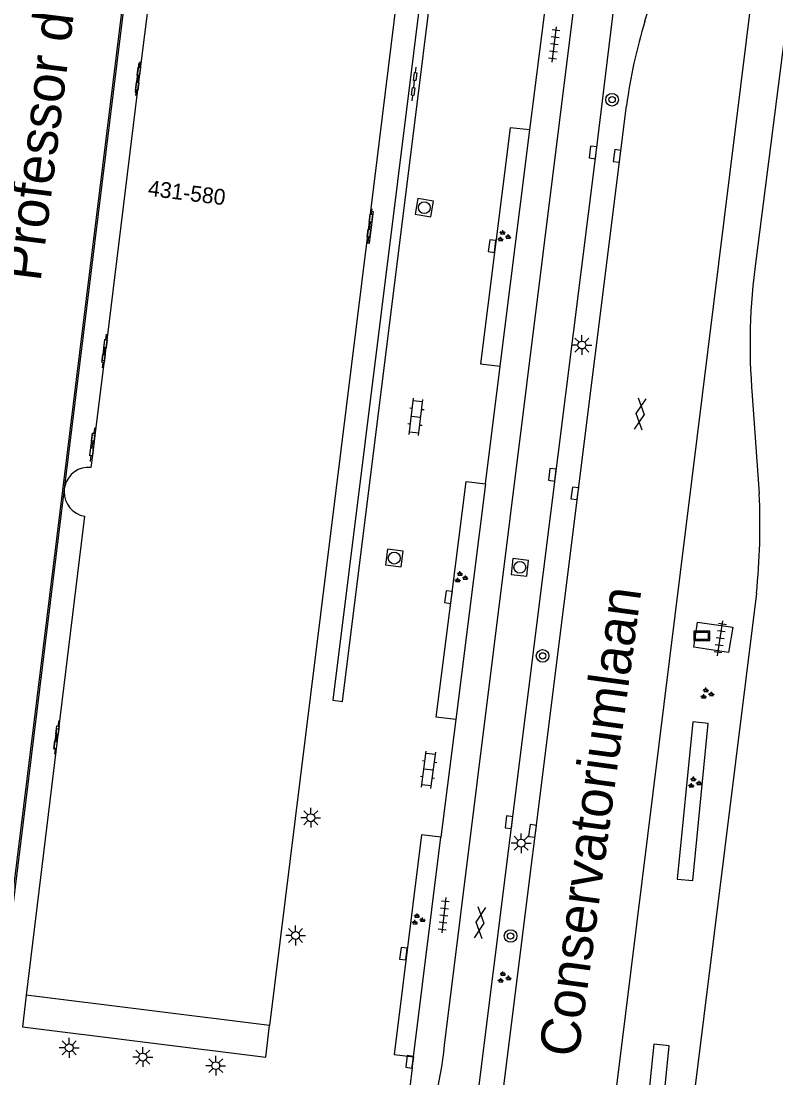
# Model space of a CAD drawing. Extents: x 131000 to 133014, y 396499 to 399001.
# Drawn here: x 131618.1 to 131665.8, y 397040.1 to 397107 of the extents above; entities that cross this region are included whole.
import ezdxf

# ---------------------------------------------------------------- set-up
doc = ezdxf.new("R2010")
doc.units = 0
for name, color, linetype in [('gg-anno-huisnummerreeks BGT', 7, 'Continuous'), ('gg-anno-openbare ruimte label', 7, 'Continuous'), ('gg-bbg-hoofdgebouw', 7, 'Continuous'), ('gg-bbg-onder overbouw', 7, 'Continuous'), ('gg-bbg-pand overbouw', 7, 'Continuous'), ('gg-knt-verharding', 7, 'Continuous'), ('gt-grn-afwateringsgoot', 7, 'Continuous'), ('gt-grn-groengrens', 7, 'Continuous'), ('gt-symb-afwateringsgoot', 7, 'Continuous'), ('gt-symb-boom', 7, 'Continuous'), ('gt-symb-gesloten verharding', 7, 'Continuous'), ('gt-symb-groenvak', 7, 'Continuous'), ('gt-symb-klinker verharding', 7, 'Continuous'), ('gt-symb-kolk', 7, 'Continuous'), ('gt-symb-lichtmast', 7, 'Continuous'), ('gt-symb-reclamebord', 7, 'Continuous'), ('gt-symb-rioolschacht', 7, 'Continuous'), ('gt-symb-tegel verharding', 7, 'Continuous')]:
    doc.layers.add(name, color=color, linetype=linetype)

# ---------------------------------------------------------------- blocks, each defined once
blk = doc.blocks.new('gt0-GRVAK')
at = {"layer": 'gt-symb-groenvak'}
for p, q in [((-0.11, 0.189), (-0.228, 0.24)), ((-0.182, 0.153), (0.088, 0.153)), ((-0.091, 0.211), (-0.156, 0.322)), ((-0.047, 0.214), (-0.047, 0.393)), ((-0.004, 0.211), (0.061, 0.322)), ((0.015, 0.189), (0.133, 0.24)), ((0.262, -0.052), (0.197, 0.059)), ((0.305, -0.049), (0.305, 0.13)), ((0.349, -0.052), (0.414, 0.059)), ((-0.245, -0.228), (-0.363, -0.177)), ((-0.318, -0.264), (-0.047, -0.264)), ((-0.226, -0.206), (-0.291, -0.095)), ((-0.183, -0.203), (-0.183, -0.024)), ((-0.139, -0.206), (-0.074, -0.095)), ((-0.12, -0.228), (-0.002, -0.177)), ((0.243, -0.074), (0.125, -0.023)), ((0.17, -0.11), (0.441, -0.11)), ((0.368, -0.074), (0.486, -0.023))]:
    blk.add_line(p, q, dxfattribs=at)
blk = doc.blocks.new('gt0-BOOM')
at = {"layer": 'gt-symb-boom'}
for radius in [0.4, 0.2]:
    blk.add_circle((0, 0), radius, dxfattribs=at)
blk = doc.blocks.new('gt0-TEG1')
at = {"layer": 'gt-symb-tegel verharding'}
for p, q in [((-1.125, 0), (1.125, 0)), ((-0.9, -0.25), (-0.9, 0.25)), ((-0.45, -0.25), (-0.45, 0.25)), ((0, -0.25), (0, 0.25)), ((0.45, -0.25), (0.45, 0.25)), ((0.9, -0.25), (0.9, 0.25))]:
    blk.add_line(p, q, dxfattribs=at)
blk = doc.blocks.new('gt0-RBORD')
at = {"layer": 'gt-symb-reclamebord'}
blk.add_lwpolyline([(-0.5, 0.295), (-0.5, -0.295), (0.5, -0.295), (0.5, 0.295), (-0.5, 0.295)], dxfattribs=at)
blk.add_lwpolyline([(-0.417, -0.212), (0.417, -0.212), (0.417, 0.212), (-0.417, 0.212)], close=True, dxfattribs=at)
blk = doc.blocks.new('gt0-KOLK')
at = {"layer": 'gt-symb-kolk'}
blk.add_lwpolyline([(0, 0), (0.375, 0), (0.375, 0.4), (-0.375, 0.4), (-0.375, 0), (0, 0)], dxfattribs=at)
blk = doc.blocks.new('gt0-GESVH1')
at = {"layer": 'gt-symb-gesloten verharding'}
for p, q in [((-0.992, -0.261), (0.008, 0.239)), ((0.008, -0.261), (-0.992, 0.239)), ((0.008, 0.239), (1.008, -0.261)), ((1.008, 0.239), (0.008, -0.261))]:
    blk.add_line(p, q, dxfattribs=at)
blk = doc.blocks.new('gt0-LMAST')
at = {"layer": 'gt-symb-lichtmast'}
for p, q in [((-0.182, 0.173), (-0.447, 0.438)), ((-0.005, 0.246), (-0.005, 0.621)), ((0.172, 0.173), (0.437, 0.438)), ((-0.255, -0.004), (-0.63, -0.004)), ((-0.182, -0.181), (-0.447, -0.446)), ((-0.005, -0.254), (-0.005, -0.629)), ((0.437, -0.446), (0.172, -0.181)), ((0.245, -0.004), (0.62, -0.004))]:
    blk.add_line(p, q, dxfattribs=at)
blk.add_circle((-0.005, -0.004), 0.25, dxfattribs=at)
blk = doc.blocks.new('gt0-KL1')
at = {"layer": 'gt-symb-klinker verharding'}
for p, q in [((-1.15, 0.3), (1.15, 0.3)), ((-1, -0.3), (-1, 0.3)), ((-0.5, 0.3), (-0.5, 0.45)), ((0, -0.3), (0, 0.3)), ((0.5, 0.3), (0.5, 0.45)), ((1, -0.3), (1, 0.3)), ((-1.15, -0.3), (1.15, -0.3)), ((-0.5, -0.45), (-0.5, -0.3)), ((0.5, -0.45), (0.5, -0.3))]:
    blk.add_line(p, q, dxfattribs=at)
blk = doc.blocks.new('gt0-RS')
at = {"layer": 'gt-symb-rioolschacht'}
blk.add_lwpolyline([(-0.5, -0.5), (0.5, -0.5), (0.5, 0.5), (-0.5, 0.5)], close=True, dxfattribs=at)
blk.add_circle((0, 0), 0.375, dxfattribs=at)
blk = doc.blocks.new('gt0-AFWGT_1')
at = {"layer": 'gt-symb-afwateringsgoot'}
for p, q in [((-1.076, 0), (-0.726, 0)), ((-0.225, 0), (0.225, 0)), ((0.725, 0), (1.075, 0))]:
    blk.add_line(p, q, dxfattribs=at)
for points in [[(-0.726, 0.075), (-0.225, 0.075), (-0.225, -0.075), (-0.726, -0.075)], [(0.225, 0.075), (0.725, 0.075), (0.725, -0.075), (0.225, -0.075)]]:
    blk.add_lwpolyline(points, close=True, dxfattribs=at)

msp = doc.modelspace()

# ---------------------------------------------------------------- linework, layer by layer
at = {"layer": 'gg-bbg-hoofdgebouw'}
for p, q in [((131642.751, 397115.402), (131640.218, 397094.939)), ((131626.157, 397107.969), (131625.703, 397104.29)), ((131625.703, 397104.29), (131625.477, 397102.45)), ((131625.477, 397102.45), (131623.543, 397086.782)), ((131640.218, 397094.939), (131639.967, 397092.913)), ((131639.967, 397092.913), (131633.838, 397043.417)), ((131623.543, 397086.782), (131623.386, 397085.509)), ((131623.386, 397085.509), (131622.8, 397080.76)), ((131622.8, 397080.76), (131622.643, 397079.484)), ((131622.643, 397079.484), (131622.551, 397078.738)), ((131622.15, 397075.649), (131620.505, 397062.183)), ((131620.505, 397062.183), (131620.351, 397060.92)), ((131620.351, 397060.92), (131618.448, 397045.343))]:
    msp.add_line(p, q, dxfattribs=at)
for centre, radius, start, end in [((131622.408, 397077.188), 1.557, 84.73393, 166.54397), ((131622.386, 397077.185), 1.536, 166.23704, 179.35085), ((131622.411, 397077.188), 1.561, 179.48698, 260.37772)]:
    msp.add_arc(centre, radius, start, end, dxfattribs=at)
at = {"layer": 'gg-bbg-onder overbouw'}
msp.add_line((131633.838, 397043.417), (131618.448, 397045.343), dxfattribs=at)
at = {"layer": 'gg-bbg-pand overbouw'}
msp.add_lwpolyline([(131618.448, 397045.343), (131618.214, 397043.335), (131633.596, 397041.421), (131633.838, 397043.417)], dxfattribs=at)
at = {"layer": 'gg-knt-verharding'}
for p, q in [((131655, 397033.279), (131668.87, 397145.099)), ((131671.312, 397144.795), (131664.589, 397091.808)), ((131657.573, 397106.97), (131659.222, 397112.319)), ((131650.3, 397100.099), (131651.243, 397107.552)), ((131647.987, 397034.254), (131656.406, 397101.621)), ((131648.419, 397085.15), (131650.3, 397100.099)), ((131647.488, 397077.697), (131648.419, 397085.15)), ((131664.358, 397083.283), (131664.798, 397077.073)), ((131647.488, 397077.697), (131645.613, 397062.795)), ((131664.625, 397070.775), (131659.89, 397032.634)), ((131645.613, 397062.795), (131644.663, 397055.351)), ((131642.933, 397041.441), (131644.663, 397055.351)), ((131642.933, 397041.441), (131642.89, 397041.102))]:
    msp.add_line(p, q, dxfattribs=at)
for points in [[(131644.907, 397042.18), (131654.248, 397117.309), (131658.448, 397151.313)], [(131646.029, 397034.524), (131646.473, 397035.992), (131646.975, 397038.641), (131651.132, 397071.966), (131654.486, 397098.638), (131660.271, 397146.067)], [(131650.3, 397100.099), (131649.058, 397100.228), (131647.172, 397085.298), (131648.419, 397085.15)], [(131645.613, 397062.795), (131644.374, 397062.923), (131645.35, 397070.506), (131646.263, 397077.838), (131647.488, 397077.697)], [(131663.127, 397068.62), (131662.862, 397067.019), (131660.668, 397067.361), (131660.901, 397068.954), (131663.127, 397068.62)], [(131644.663, 397055.351), (131643.438, 397055.492), (131641.716, 397041.596), (131642.933, 397041.441)]]:
    msp.add_lwpolyline(points, dxfattribs=at)
for centre, radius, start, end in [((131689.559, 397097.19), 33.448, 162.99809, 172.38699), ((131701.961, 397086.53), 37.743, 171.96096, 184.93474), ((131622.562, 397075.082), 42.283, 354.15394, 2.69913), ((131612.199, 397045.916), 32.92, 340.755, 353.48407), ((131629.7, 397041.673), 13.203, 332.92961, 357.51999)]:
    msp.add_arc(centre, radius, start, end, dxfattribs=at)
at = {"layer": 'gt-grn-afwateringsgoot'}
msp.add_line((131620.85, 397077.202), (131620.894, 397077.55), dxfattribs=at)
for points in [[(131620.894, 397077.55), (131629.66, 397148.536), (131629.529, 397148.555), (131616.59, 397043.813), (131616.719, 397043.804), (131620.85, 397077.202)], [(131648.663, 397145.819), (131648.046, 397145.898), (131637.843, 397064.001), (131638.456, 397063.934), (131648.663, 397145.819)], [(131625.703, 397104.29), (131625.572, 397104.306), (131625.343, 397102.467), (131625.477, 397102.45)], [(131640.218, 397094.939), (131640.382, 397094.917), (131640.131, 397092.891), (131639.967, 397092.913)], [(131623.543, 397086.782), (131623.408, 397086.8), (131623.251, 397085.527), (131623.386, 397085.509)], [(131622.8, 397080.76), (131622.623, 397080.782), (131622.464, 397079.506), (131622.643, 397079.484)], [(131620.505, 397062.183), (131620.373, 397062.199), (131620.212, 397060.938), (131620.351, 397060.92)]]:
    msp.add_lwpolyline(points, dxfattribs=at)
at = {"layer": 'gt-grn-groengrens'}
for points in [[(131659.601, 397052.68), (131660.592, 397052.597), (131661.571, 397062.536), (131660.604, 397062.636), (131659.601, 397052.68)], [(131657.53, 397036.277), (131658.521, 397036.194), (131659.107, 397042.146), (131658.132, 397042.248), (131657.53, 397036.277)]]:
    msp.add_lwpolyline(points, dxfattribs=at)

# ---------------------------------------------------------------- block references
at = {"layer": 'gt-symb-afwateringsgoot'}
for p, xscale, yscale, rotation in [((131625.522, 397103.323), 1.000045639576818, 1.0000456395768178, 82.89896755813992), ((131642.979, 397102.991), 1.000045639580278, 1.000045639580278, 82.89896755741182), ((131640.177, 397094.029), 0.9999532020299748, 0.999953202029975, -97.05838821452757), ((131623.402, 397086.096), 1.0000312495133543, 1.000031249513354, 82.96381424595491), ((131622.639, 397080.18), 1.000045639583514, 1.000045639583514, -97.10103244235), ((131620.372, 397061.65), 0.9999249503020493, 0.9999249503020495, -97.27515612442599)]:
    msp.add_blockref('gt0-AFWGT_1', p, dxfattribs=dict(at, xscale=xscale, yscale=yscale, rotation=rotation))
at = {"layer": 'gt-symb-boom'}
for p in [(131655.497, 397102), (131651.104, 397066.813), (131649.077, 397049.088)]:
    msp.add_blockref('gt0-BOOM', p, dxfattribs=at)
at = {"layer": 'gt-symb-gesloten verharding'}
for p, rotation in [((131657.257, 397082.115), 82.93185994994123), ((131647.158, 397049.936), -96.606034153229)]:
    msp.add_blockref('gt0-GESVH1', p, dxfattribs=dict(at, rotation=rotation))
at = {"layer": 'gt-symb-groenvak'}
for p in [(131648.625, 397093.353), (131645.92, 397071.774), (131661.474, 397064.41), (131660.691, 397058.779), (131643.214, 397050.129), (131648.643, 397046.452)]:
    msp.add_blockref('gt0-GRVAK', p, dxfattribs=at)
at = {"layer": 'gt-symb-klinker verharding'}
for p, rotation in [((131643.098, 397081.928), 82.93185994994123), ((131643.896, 397059.61), 82.46974665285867)]:
    msp.add_blockref('gt0-KL1', p, dxfattribs=dict(at, rotation=rotation))
at = {"layer": 'gt-symb-kolk'}
for p, rotation in [((131654.486, 397098.638), 82.81812146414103), ((131656.009, 397098.422), 82.8749836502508), ((131648.106, 397092.712), 82.76127349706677), ((131651.912, 397078.243), 82.93185994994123), ((131653.336, 397077.068), 82.87498365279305), ((131645.35, 397070.506), 82.64762064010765), ((131649.18, 397056.263), 82.8749836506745), ((131650.664, 397055.714), 82.87498364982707), ((131642.504, 397047.945), 82.93185994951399), ((131642.89, 397041.102), 82.76127349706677)]:
    msp.add_blockref('gt0-KOLK', p, dxfattribs=dict(at, rotation=rotation))
at = {"layer": 'gt-symb-lichtmast'}
for p in [(131653.591, 397086.481), (131636.449, 397056.573), (131649.75, 397054.961), (131635.492, 397049.123), (131621.179, 397042.018), (131625.831, 397041.432), (131630.441, 397040.888)]:
    msp.add_blockref('gt0-LMAST', p, dxfattribs=at)
at = {"layer": 'gt-symb-reclamebord'}
msp.add_blockref('gt0-RBORD', (131661.169, 397068.088), dxfattribs=at)
at = {"layer": 'gt-symb-rioolschacht'}
for p, rotation in [((131643.621, 397095.17), -99.50001059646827), ((131641.723, 397072.997), -96.89054832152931), ((131649.665, 397072.412), -96.25793391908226)]:
    msp.add_blockref('gt0-RS', p, dxfattribs=dict(at, rotation=rotation))
at = {"layer": 'gt-symb-tegel verharding'}
for p, rotation in [((131651.843, 397105.494), 82.93185994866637), ((131662.332, 397067.921), 81.08396326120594), ((131644.853, 397050.397), -96.60603415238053)]:
    msp.add_blockref('gt0-TEG1', p, dxfattribs=dict(at, rotation=rotation))

# ---------------------------------------------------------------- texts
at = {"layer": 'gg-anno-huisnummerreeks BGT'}
msp.add_text('431-580', height=1, rotation=352.9, dxfattribs=at).set_placement((131626.118, 397095.923))
at = {"layer": 'gg-anno-openbare ruimte label'}
for s, rotation, p in [('Professor de Moorplein', 82.9, (131619.358, 397090.446)), ('Conservatoriumlaan', 82.3, (131653.346, 397041.347))]:
    msp.add_text(s, height=2.5, rotation=rotation, dxfattribs=at).set_placement(p)

doc.saveas('drawing.dxf')
